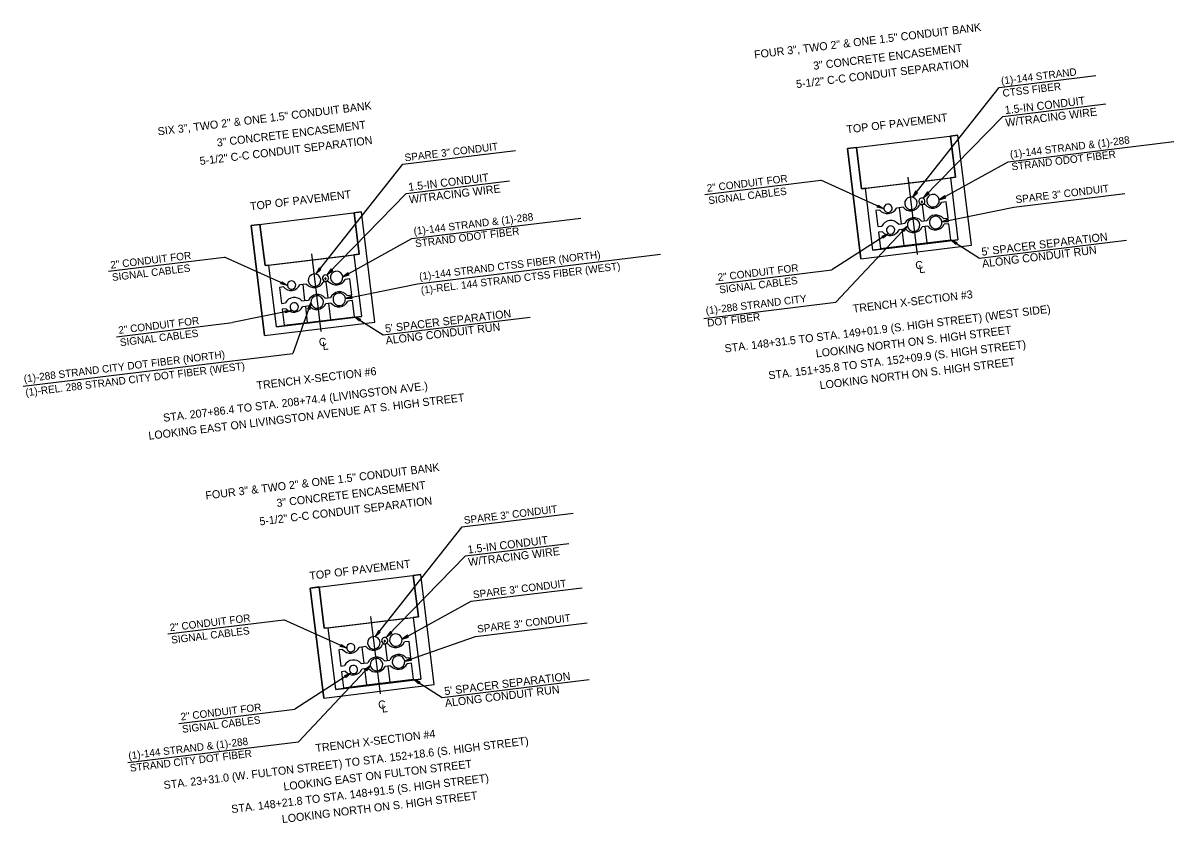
# Model space of a CAD drawing. Extents: x 91401 to 1830080, y 35587 to 712188.
# Drawn here: x 1828619 to 1829481, y 710434 to 711034 of the extents above; entities that cross this region are included whole.
import ezdxf

# ---------------------------------------------------------------- set-up
doc = ezdxf.new("R2010")
doc.units = 0
doc.layers.add('Default', color=7, linetype='Continuous')
doc.layers.add('SH_Text', color=7, linetype='Continuous')

# ---------------------------------------------------------------- blocks, each defined once
blk = doc.blocks.new('POINT_DISPLAY')
at = {"layer": 'Default'}
blk.add_line((0, 0), (0, 0), dxfattribs=at)

msp = doc.modelspace()

# ---------------------------------------------------------------- linework, layer by layer
at = {"layer": 'SH_Text'}
for p, q in [((1829350.31, 710985.54), (1829422.8, 710994.39)), ((1829285.23, 710903.22), (1829350.31, 710985.54)), ((1829352.97, 710963.73), (1829430.34, 710973.18)), ((1829293.65, 710903.03), (1829352.97, 710963.73)), ((1829319.39, 710949.8), (1829313.8, 710949.12)), ((1829317.58, 710918.16), (1829313.8, 710949.12)), ((1829329.47, 710867.28), (1829319.39, 710949.8)), ((1829243.26, 710940.51), (1829236.55, 710939.69)), ((1829236.55, 710939.69), (1829246.63, 710857.17)), ((1829247.04, 710909.55), (1829243.26, 710940.51)), ((1829357.12, 710929.79), (1829481.34, 710944.96)), ((1828903.24, 710927.93), (1828987.77, 710938.25)), ((1828838.16, 710845.62), (1828903.24, 710927.93)), ((1829305.38, 710901.24), (1829357.12, 710929.79)), ((1828905.9, 710906.13), (1828983.27, 710915.58)), ((1829129.75, 710905.34), (1829216.65, 710915.95)), ((1829263.85, 710894.59), (1829216.65, 710915.95)), ((1829281.76, 710918.38), (1829288.85, 710860.29)), ((1829313.74, 710917.69), (1829319.4, 710871.37)), ((1828846.57, 710845.42), (1828905.9, 710906.13)), ((1829250.02, 710909.91), (1829247.04, 710909.55)), ((1829255.68, 710863.59), (1829250.02, 710909.91)), ((1829361.26, 710895.89), (1829444.54, 710906.06)), ((1829307.37, 710884.89), (1829361.26, 710895.89)), ((1828872.32, 710892.2), (1828866.73, 710891.52)), ((1828870.51, 710860.56), (1828866.73, 710891.52)), ((1828882.39, 710809.68), (1828872.32, 710892.2)), ((1828910.04, 710872.19), (1829036.73, 710887.65)), ((1828796.19, 710882.9), (1828789.48, 710882.09)), ((1828789.48, 710882.09), (1828799.55, 710799.56)), ((1828799.97, 710851.95), (1828796.19, 710882.9)), ((1829281.5, 710881.74), (1829227.81, 710824.53)), ((1828858.3, 710843.63), (1828910.04, 710872.19)), ((1829267.22, 710876.02), (1829224.85, 710848.81)), ((1829255.68, 710863.59), (1829319.4, 710871.37)), ((1829255.68, 710863.59), (1829319.4, 710871.37)), ((1829255.68, 710863.59), (1829319.4, 710871.37)), ((1829319.4, 710871.37), (1829255.68, 710863.59)), ((1829314.02, 710871.33), (1829335.52, 710857.61)), ((1829335.52, 710857.61), (1829445.72, 710871.06)), ((1829246.63, 710857.17), (1829329.47, 710867.28)), ((1829246.63, 710857.17), (1829329.47, 710867.28)), ((1828682.67, 710847.74), (1828769.58, 710858.35)), ((1828816.77, 710836.98), (1828769.58, 710858.35)), ((1828834.69, 710860.77), (1828841.78, 710802.69)), ((1828866.67, 710860.09), (1828872.32, 710813.77)), ((1828914.18, 710838.28), (1829096.36, 710860.53)), ((1828802.95, 710852.31), (1828799.97, 710851.95)), ((1828808.6, 710805.99), (1828802.95, 710852.31)), ((1829137.95, 710838.2), (1829224.85, 710848.81)), ((1828860.3, 710827.29), (1828914.18, 710838.28)), ((1828820.14, 710818.41), (1828775.57, 710809.24)), ((1828834.42, 710824.13), (1828820.77, 710786.21)), ((1829129.03, 710812.47), (1829227.81, 710824.53)), ((1828799.55, 710799.56), (1828882.39, 710809.68)), ((1828799.55, 710799.56), (1828882.39, 710809.68)), ((1828808.6, 710805.99), (1828872.32, 710813.77)), ((1828808.6, 710805.99), (1828872.32, 710813.77)), ((1828808.6, 710805.99), (1828872.32, 710813.77)), ((1828872.32, 710813.77), (1828808.6, 710805.99)), ((1828866.95, 710813.72), (1828888.44, 710800)), ((1828888.44, 710800), (1828998.65, 710813.46)), ((1828688.67, 710798.63), (1828775.57, 710809.24)), ((1828618.56, 710761.52), (1828820.77, 710786.21)), ((1828947.66, 710656.2), (1829031.03, 710666.38)), ((1828882.58, 710573.89), (1828947.66, 710656.2)), ((1828950.32, 710634.4), (1829027.69, 710643.84)), ((1828891, 710573.69), (1828950.32, 710634.4)), ((1828916.74, 710620.46), (1828911.15, 710619.78)), ((1828926.82, 710537.94), (1828916.74, 710620.46)), ((1828840.61, 710611.17), (1828833.9, 710610.35)), ((1828844.39, 710580.21), (1828840.61, 710611.17)), ((1828914.93, 710588.82), (1828911.15, 710619.78)), ((1828833.9, 710610.35), (1828843.98, 710527.83)), ((1828954.46, 710600.45), (1829037.59, 710610.6)), ((1828902.72, 710571.9), (1828954.46, 710600.45)), ((1828727.1, 710576), (1828814, 710586.61)), ((1828861.19, 710565.25), (1828814, 710586.61)), ((1828879.11, 710589.04), (1828886.2, 710530.95)), ((1828911.09, 710588.36), (1828916.75, 710542.04)), ((1828847.37, 710580.58), (1828844.39, 710580.21)), ((1828853.02, 710534.26), (1828847.37, 710580.58)), ((1828957.69, 710574.03), (1829041.35, 710584.25)), ((1828904.72, 710555.56), (1828957.69, 710574.03)), ((1828878.85, 710552.4), (1828825.16, 710495.19)), ((1828864.57, 710546.68), (1828822.2, 710519.47)), ((1828843.98, 710527.83), (1828926.82, 710537.94)), ((1828843.98, 710527.83), (1828926.82, 710537.94)), ((1828853.02, 710534.26), (1828916.75, 710542.04)), ((1828853.02, 710534.26), (1828916.75, 710542.04)), ((1828853.02, 710534.26), (1828916.75, 710542.04)), ((1828853.02, 710534.26), (1828916.75, 710542.04)), ((1828916.75, 710542.04), (1828853.02, 710534.26)), ((1828911.37, 710541.99), (1828932.87, 710528.27)), ((1828932.87, 710528.27), (1829043.07, 710541.72)), ((1828735.29, 710508.86), (1828822.2, 710519.47)), ((1828697.13, 710479.56), (1828825.16, 710495.19))]:
    msp.add_line(p, q, dxfattribs=at)
for points in [[(1829236.55, 710939.69), (1829307.1, 710948.3), (1829319.39, 710949.8), (1829319.39, 710949.8)], [(1829243.26, 710940.51), (1829247.04, 710909.55), (1829317.58, 710918.16), (1829313.8, 710949.12)], [(1829313.8, 710949.12), (1829317.58, 710918.16), (1829313.74, 710917.69)], [(1829329.47, 710867.28), (1829319.39, 710949.8)], [(1829246.63, 710857.17), (1829236.55, 710939.69)], [(1829250.02, 710909.91), (1829290.58, 710914.87), (1829313.74, 710917.69), (1829319.4, 710871.37)], [(1829250.02, 710909.91), (1829308.4, 710917.04), (1829313.74, 710917.69), (1829319.4, 710871.37)], [(1829250.02, 710909.91), (1829272.77, 710912.69), (1829313.74, 710917.69), (1829319.4, 710871.37)], [(1829255.68, 710863.59), (1829250.02, 710909.91)], [(1829255.68, 710863.59), (1829250.02, 710909.91)], [(1829294.72, 710897.76), (1829290.67, 710897.27)], [(1829292.69, 710897.52), (1829294.16, 710885.48)], [(1829308.64, 710887.25), (1829312.03, 710887.66), (1829310.56, 710899.7), (1829307.17, 710899.28)], [(1828789.48, 710882.09), (1828860.02, 710890.7), (1828872.32, 710892.2), (1828872.32, 710892.2)], [(1828796.19, 710882.9), (1828799.97, 710851.95), (1828870.51, 710860.56), (1828866.73, 710891.52)], [(1828866.73, 710891.52), (1828870.51, 710860.56), (1828866.67, 710860.09)], [(1828882.39, 710809.68), (1828872.32, 710892.2)], [(1829260.82, 710893.62), (1829257.89, 710893.27), (1829259.36, 710881.23), (1829262.29, 710881.58)], [(1829275.29, 710895.39), (1829273.27, 710895.14)], [(1829278.22, 710895.75), (1829275.29, 710895.39), (1829276.76, 710883.35)], [(1828799.55, 710799.56), (1828789.48, 710882.09)], [(1829274.74, 710883.11), (1829276.76, 710883.35)], [(1829277.29, 710879.06), (1829275.26, 710878.81)], [(1829276.76, 710883.35), (1829279.69, 710883.71)], [(1829280.21, 710879.42), (1829277.29, 710879.06), (1829278.76, 710867.02)], [(1829278.76, 710867.02), (1829314.02, 710871.33), (1829312.55, 710883.37), (1829309.17, 710882.95)], [(1829292.14, 710885.23), (1829296.19, 710885.72)], [(1829296.72, 710881.43), (1829292.66, 710880.94)], [(1829294.69, 710881.18), (1829296.16, 710869.15)], [(1829262.81, 710877.29), (1829259.89, 710876.93), (1829261.35, 710864.9), (1829278.76, 710867.02)], [(1828802.95, 710852.31), (1828843.51, 710857.26), (1828866.67, 710860.09), (1828872.32, 710813.77)], [(1828802.95, 710852.31), (1828861.32, 710859.44), (1828866.67, 710860.09), (1828872.32, 710813.77)], [(1828802.95, 710852.31), (1828825.7, 710855.09), (1828866.67, 710860.09), (1828872.32, 710813.77)], [(1828808.6, 710805.99), (1828802.95, 710852.31)], [(1828808.6, 710805.99), (1828802.95, 710852.31)], [(1828813.74, 710836.02), (1828810.82, 710835.66), (1828812.29, 710823.62), (1828815.21, 710823.98)], [(1828828.22, 710837.79), (1828826.19, 710837.54)], [(1828831.14, 710838.14), (1828828.22, 710837.79), (1828829.69, 710825.75)], [(1828847.65, 710840.16), (1828843.59, 710839.66)], [(1828845.62, 710839.91), (1828847.09, 710827.87)], [(1828861.57, 710829.64), (1828864.96, 710830.06), (1828863.49, 710842.09), (1828860.1, 710841.68)], [(1828845.06, 710827.63), (1828849.12, 710828.12)], [(1828815.73, 710819.69), (1828812.81, 710819.33), (1828814.28, 710807.29), (1828831.68, 710809.42)], [(1828827.66, 710825.5), (1828829.69, 710825.75)], [(1828830.21, 710821.46), (1828828.19, 710821.21)], [(1828829.69, 710825.75), (1828832.61, 710826.11)], [(1828833.14, 710821.81), (1828830.21, 710821.46), (1828831.68, 710809.42)], [(1828831.68, 710809.42), (1828866.95, 710813.72), (1828865.48, 710825.76), (1828862.09, 710825.35)], [(1828849.64, 710823.83), (1828845.59, 710823.33)], [(1828847.61, 710823.58), (1828849.08, 710811.54)], [(1828833.9, 710610.35), (1828904.44, 710618.96), (1828916.74, 710620.46), (1828916.74, 710620.46)], [(1828926.82, 710537.94), (1828916.74, 710620.46)], [(1828840.61, 710611.17), (1828844.39, 710580.21), (1828914.93, 710588.82), (1828911.15, 710619.78)], [(1828911.15, 710619.78), (1828914.93, 710588.82), (1828911.09, 710588.36)], [(1828843.98, 710527.83), (1828833.9, 710610.35)], [(1828847.37, 710580.58), (1828887.93, 710585.53), (1828911.09, 710588.36), (1828916.75, 710542.04)], [(1828847.37, 710580.58), (1828887.93, 710585.53), (1828911.09, 710588.36), (1828916.75, 710542.04)], [(1828847.37, 710580.58), (1828905.74, 710587.7), (1828911.09, 710588.36), (1828916.75, 710542.04)], [(1828847.37, 710580.58), (1828870.12, 710583.35), (1828911.09, 710588.36), (1828916.75, 710542.04)], [(1828853.02, 710534.26), (1828847.37, 710580.58)], [(1828853.02, 710534.26), (1828847.37, 710580.58)], [(1828892.07, 710568.42), (1828888.02, 710567.93)], [(1828890.04, 710568.18), (1828891.51, 710556.14)], [(1828905.99, 710557.91), (1828909.38, 710558.32), (1828907.91, 710570.36), (1828904.52, 710569.94)], [(1828858.16, 710564.28), (1828855.24, 710563.93), (1828856.71, 710551.89), (1828859.63, 710552.25)], [(1828872.64, 710566.05), (1828870.61, 710565.8)], [(1828875.57, 710566.41), (1828872.64, 710566.05), (1828874.11, 710554.01)], [(1828872.08, 710553.77), (1828874.11, 710554.01)], [(1828874.11, 710554.01), (1828877.04, 710554.37)], [(1828876.1, 710537.68), (1828911.37, 710541.99), (1828909.9, 710554.03), (1828906.51, 710553.61)], [(1828889.49, 710555.89), (1828893.54, 710556.39)], [(1828894.06, 710552.09), (1828890.01, 710551.6)], [(1828892.04, 710551.85), (1828893.51, 710539.81)], [(1828860.16, 710547.95), (1828857.23, 710547.6), (1828858.7, 710535.56), (1828876.1, 710537.68)], [(1828874.63, 710549.72), (1828872.61, 710549.47)], [(1828877.56, 710550.08), (1828874.63, 710549.72), (1828876.1, 710537.68)]]:
    msp.add_lwpolyline(points, dxfattribs=at)
for points in [[(1829288.99, 710906.63), (1829287.68, 710907.66), (1829285.23, 710903.22)], [(1829297.76, 710905.99), (1829296.58, 710907.16), (1829293.65, 710903.03)], [(1829258.95, 710895.89), (1829259.64, 710897.41), (1829263.85, 710894.59)], [(1829310.21, 710902.76), (1829309.45, 710904.25), (1829305.38, 710901.24)], [(1829278.69, 710877.52), (1829277.47, 710878.66), (1829281.5, 710881.74)], [(1829312.44, 710885.09), (1829312.1, 710886.72), (1829307.37, 710884.89)], [(1829263.46, 710872.61), (1829262.56, 710874.02), (1829267.22, 710876.02)], [(1829318.68, 710869.33), (1829317.78, 710867.93), (1829314.02, 710871.33)], [(1828841.91, 710849.03), (1828840.6, 710850.06), (1828838.16, 710845.62)], [(1828850.69, 710848.38), (1828849.51, 710849.56), (1828846.57, 710845.42)], [(1828863.14, 710845.16), (1828862.38, 710846.64), (1828858.3, 710843.63)], [(1828811.87, 710838.29), (1828812.56, 710839.8), (1828816.77, 710836.98)], [(1828865.36, 710827.48), (1828865.03, 710829.12), (1828860.3, 710827.29)], [(1828815.42, 710816.59), (1828815.08, 710818.22), (1828820.14, 710818.41)], [(1828833.51, 710819.15), (1828831.95, 710819.71), (1828834.42, 710824.13)], [(1828871.61, 710811.73), (1828870.71, 710810.33), (1828866.95, 710813.72)], [(1828886.33, 710577.29), (1828885.03, 710578.33), (1828882.58, 710573.89)], [(1828895.11, 710576.65), (1828893.93, 710577.82), (1828891, 710573.69)], [(1828856.3, 710566.55), (1828856.98, 710568.07), (1828861.19, 710565.25)], [(1828907.56, 710573.42), (1828906.8, 710574.91), (1828902.72, 710571.9)], [(1828876.03, 710548.18), (1828874.82, 710549.32), (1828878.85, 710552.4)], [(1828909.73, 710556.3), (1828909.22, 710557.89), (1828904.72, 710555.56)], [(1828860.81, 710543.28), (1828859.91, 710544.68), (1828864.57, 710546.68)], [(1828916.03, 710539.99), (1828915.13, 710538.59), (1828911.37, 710541.99)]]:
    msp.add_lwpolyline(points, close=True, dxfattribs=at)
for centre, radius, start, end in [((1829300.71, 710900.67), 4.7, 6.96143, 186.96143), ((1829266.96, 710894.97), 3.13, 6.96143, 186.96143), ((1829283.96, 710900.5), 7.45, 219.64855, 334.27431), ((1829284.17, 710898.65), 4.7, 6.96143, 186.96143), ((1829284.17, 710898.65), 4.7, 186.96143, 6.96143), ((1829292.37, 710900.25), 2.35, 6.96143, 186.96143), ((1829292.37, 710900.25), 2.35, 186.96143, 6.96143), ((1829292.35, 710899.85), 0.5, 6.96143, 186.96143), ((1829292.35, 710899.85), 0.5, 186.96143, 6.96143), ((1829300.46, 710902.52), 7.45, 219.64855, 334.27431), ((1829300.71, 710900.67), 4.7, 186.96143, 6.96143), ((1829266.55, 710898.38), 7.45, 219.64855, 334.27431), ((1829266.96, 710894.97), 3.13, 186.96143, 6.96143), ((1829286.4, 710880.48), 7.45, 39.64855, 154.27431), ((1829302.9, 710882.49), 7.45, 39.64855, 154.27431), ((1829302.71, 710884.32), 4.7, 6.96143, 186.96143), ((1829269, 710878.35), 7.45, 39.64855, 154.27431), ((1829268.55, 710882.05), 7.45, 219.64855, 334.27431), ((1829268.95, 710878.63), 3.13, 6.96143, 186.96143), ((1829268.95, 710878.63), 3.13, 186.96143, 6.96143), ((1829285.95, 710884.17), 7.45, 219.64855, 334.27431), ((1829286.16, 710882.31), 4.7, 6.96143, 186.96143), ((1829286.16, 710882.31), 4.7, 186.96143, 6.96143), ((1829302.45, 710886.19), 7.45, 219.64855, 334.27431), ((1829302.71, 710884.32), 4.7, 186.96143, 6.96143), ((1828837.09, 710841.04), 4.7, 6.96143, 186.96143), ((1828845.29, 710842.65), 2.35, 6.96143, 186.96143), ((1828853.64, 710843.06), 4.7, 6.96143, 186.96143), ((1828819.48, 710840.77), 7.45, 219.64855, 334.27431), ((1828819.88, 710837.36), 3.13, 6.96143, 186.96143), ((1828819.88, 710837.36), 3.13, 186.96143, 6.96143), ((1828836.88, 710842.9), 7.45, 219.64855, 334.27431), ((1828837.09, 710841.04), 4.7, 186.96143, 6.96143), ((1828845.29, 710842.65), 2.35, 186.96143, 6.96143), ((1828845.27, 710842.24), 0.5, 6.96143, 186.96143), ((1828845.27, 710842.24), 0.5, 186.96143, 6.96143), ((1828853.38, 710844.91), 7.45, 219.64855, 334.27431), ((1828853.64, 710843.06), 4.7, 186.96143, 6.96143), ((1828821.92, 710820.75), 7.45, 39.64855, 154.27431), ((1828839.33, 710822.87), 7.45, 39.64855, 154.27431), ((1828839.09, 710824.7), 4.7, 6.96143, 186.96143), ((1828855.83, 710824.89), 7.45, 39.64855, 154.27431), ((1828855.63, 710826.72), 4.7, 6.96143, 186.96143), ((1828855.63, 710826.72), 4.7, 186.96143, 6.96143), ((1828821.47, 710824.44), 7.45, 219.64855, 334.27431), ((1828821.88, 710821.02), 3.13, 6.96143, 186.96143), ((1828821.88, 710821.02), 3.13, 186.96143, 6.96143), ((1828838.87, 710826.57), 7.45, 219.64855, 334.27431), ((1828839.09, 710824.7), 4.7, 186.96143, 6.96143), ((1828855.38, 710828.58), 7.45, 219.64855, 334.27431), ((1828864.3, 710565.63), 3.13, 6.96143, 186.96143), ((1828881.52, 710569.31), 4.7, 6.96143, 186.96143), ((1828881.52, 710569.31), 4.7, 186.96143, 6.96143), ((1828889.71, 710570.92), 2.35, 6.96143, 186.96143), ((1828889.71, 710570.92), 2.35, 186.96143, 6.96143), ((1828889.69, 710570.51), 0.5, 6.96143, 186.96143), ((1828889.69, 710570.51), 0.5, 186.96143, 6.96143), ((1828897.81, 710573.18), 7.45, 219.64855, 334.27431), ((1828898.06, 710571.33), 4.7, 6.96143, 186.96143), ((1828898.06, 710571.33), 4.7, 186.96143, 6.96143), ((1828863.9, 710569.04), 7.45, 219.64855, 334.27431), ((1828864.3, 710565.63), 3.13, 186.96143, 6.96143), ((1828881.3, 710571.16), 7.45, 219.64855, 334.27431), ((1828900.25, 710553.15), 7.45, 39.64855, 154.27431), ((1828900.05, 710554.99), 4.7, 6.96143, 186.96143), ((1828866.35, 710549.01), 7.45, 39.64855, 154.27431), ((1828866.3, 710549.29), 3.13, 6.96143, 186.96143), ((1828883.75, 710551.14), 7.45, 39.64855, 154.27431), ((1828883.3, 710554.83), 7.45, 219.64855, 334.27431), ((1828883.51, 710552.97), 4.7, 6.96143, 186.96143), ((1828883.51, 710552.97), 4.7, 186.96143, 6.96143), ((1828899.8, 710556.85), 7.45, 219.64855, 334.27431), ((1828900.05, 710554.99), 4.7, 186.96143, 6.96143), ((1828865.89, 710552.71), 7.45, 219.64855, 334.27431), ((1828866.3, 710549.29), 3.13, 186.96143, 6.96143)]:
    msp.add_arc(centre, radius, start, end, dxfattribs=at)

# ---------------------------------------------------------------- block references
at = {"layer": 'SH_Text', "xscale": 1.5748, "yscale": 1.5748000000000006, "rotation": 6.96142799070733}
for p in [(1829288.02, 710867.15), (1828840.94, 710809.54), (1828885.36, 710537.81)]:
    msp.add_blockref('POINT_DISPLAY', p, dxfattribs=at)

# ---------------------------------------------------------------- texts
at = {"layer": 'SH_Text'}
for s, height, p in [('FOUR 3", TWO 2" & ONE 1.5" CONDUIT BANK', 6, (1829167, 711007.13)), ('3" CONCRETE ENCASEMENT', 6, (1829211.27, 710998.73)), ('5-1/2" C-C CONDUIT SEPARATION', 6, (1829198.44, 710984.97)), ('(1)-144 STRAND', 5.6, (1829352.05, 710987.71)), ('CTSS FIBER', 5.6, (1829353.18, 710978.44)), ('SIX 3", TWO 2" & ONE 1.5" CONDUIT BANK', 6, (1828719.92, 710949.53)), ('1.5-IN CONDUIT', 6, (1829354.85, 710965.49)), ('TOP OF PAVEMENT', 6, (1829236.2, 710951)), ('W/TRACING WIRE', 6, (1829355.35, 710956.14)), ('3" CONCRETE ENCASEMENT', 6, (1828764.19, 710941.13)), ('5-1/2" C-C CONDUIT SEPARATION', 6, (1828751.36, 710927.36)), ('(1)-144 STRAND & (1)-288 ', 5.6, (1829358.78, 710932.6)), ('SPARE 3" CONDUIT', 5.6, (1828904.98, 710930.11)), ('STRAND ODOT FIBER', 5.6, (1829359.91, 710923.33)), ('1.5-IN CONDUIT', 6, (1828907.78, 710907.89)), ('2" CONDUIT FOR ', 5.6, (1829131.52, 710907.25)), ('TOP OF PAVEMENT', 6, (1828789.12, 710893.4)), ('W/TRACING WIRE', 6, (1828908.28, 710898.54)), ('SIGNAL CABLES', 5.6, (1829132.65, 710897.98)), ('SPARE 3" CONDUIT', 5.6, (1829362.92, 710898.69)), ('(1)-144 STRAND & (1)-288 ', 5.6, (1828911.71, 710874.99)), ('STRAND ODOT FIBER ', 5.6, (1828912.84, 710865.73)), ("5' SPACER SEPARATION", 6, (1829337.4, 710859.36)), ('2" CONDUIT FOR ', 5.6, (1828684.45, 710849.64)), ('(1)-144 STRAND CTSS FIBER (NORTH)', 5.6, (1828915.85, 710841.09)), ('ALONG CONDUIT RUN', 6, (1829337.84, 710850.48)), ('SIGNAL CABLES', 5.6, (1828685.58, 710840.38)), ('(1)-REL. 144 STRAND CTSS FIBER (WEST)', 5.6, (1828917.11, 710830.77)), ('2" CONDUIT FOR ', 5.6, (1829139.69, 710840.37)), ('C', 6, (1829287.81, 710849.06)), ('L', 6, (1829290.5, 710846.26)), ('SIGNAL CABLES', 5.6, (1829140.82, 710831.11)), ('(1)-288 STRAND CITY ', 5.6, (1829130.67, 710815.45)), ('TRENCH X-SECTION #3', 6, (1829240.92, 710816.71)), ("5' SPACER SEPARATION", 6, (1828890.32, 710801.76)), ('STA. 148+31.5 TO STA. 149+01.9 (S. HIGH STREET) (WEST SIDE)', 6, (1829144.83, 710786.88)), ('2" CONDUIT FOR ', 5.6, (1828690.41, 710800.81)), ('DOT FIBER', 5.6, (1829131.8, 710806.18)), ('SIGNAL CABLES', 5.6, (1828691.54, 710791.54)), ('ALONG CONDUIT RUN', 6, (1828890.77, 710792.88)), ('LOOKING NORTH ON S. HIGH STREET', 6, (1829213.22, 710783.14)), ('C', 6, (1828840.73, 710791.45)), ('L', 6, (1828843.43, 710788.66)), ('STA. 151+35.8 TO STA. 152+09.9 (S. HIGH STREET)', 6, (1829177.66, 710766.71)), ('(1)-288 STRAND CITY DOT FIBER (NORTH)', 5.6, (1828619.48, 710764.41)), ('(1)-REL. 288 STRAND CITY DOT FIBER (WEST)', 5.6, (1828620.74, 710754.09)), ('TRENCH X-SECTION #6', 6, (1828793.99, 710759.12)), ('LOOKING NORTH ON S. HIGH STREET', 6, (1829216.13, 710759.32)), ('STA. 207+86.4 TO STA. 208+74.4 (LIVINGSTON AVE.)', 6, (1828723.98, 710734.89)), ('LOOKING EAST ON LIVINGSTON AVENUE AT S. HIGH STREET', 6, (1828712.96, 710721.46)), ('FOUR 3" & TWO 2" & ONE 1.5" CONDUIT BANK', 6, (1828755.71, 710676.71)), ('3" CONCRETE ENCASEMENT', 6, (1828808.96, 710671.02)), ('5-1/2" C-C CONDUIT SEPARATION', 6, (1828796.13, 710657.25)), ('SPARE 3" CONDUIT', 5.6, (1828949.4, 710658.37)), ('1.5-IN CONDUIT', 6, (1828952.2, 710636.15)), ('W/TRACING WIRE', 6, (1828952.7, 710626.8)), ('TOP OF PAVEMENT', 6, (1828833.61, 710616.47)), ('SPARE 3" CONDUIT', 5.6, (1828956.21, 710602.62)), ('2" CONDUIT FOR ', 5.6, (1828728.87, 710577.91)), ('SPARE 3" CONDUIT', 5.6, (1828959.36, 710576.84)), ('SIGNAL CABLES', 5.6, (1828730, 710568.64)), ("5' SPACER SEPARATION", 6, (1828934.74, 710530.02)), ('ALONG CONDUIT RUN', 6, (1828935.19, 710521.14)), ('C', 6, (1828885.16, 710519.72)), ('2" CONDUIT FOR ', 5.6, (1828737.04, 710511.03)), ('L', 6, (1828887.85, 710516.92)), ('SIGNAL CABLES', 5.6, (1828738.17, 710501.77)), ('STA. 23+31.0 (W. FULTON STREET) TO STA. 152+18.6 (S. HIGH STREET)', 6, (1828724.37, 710459.64)), ('TRENCH X-SECTION #4', 6, (1828838.13, 710487.35)), ('(1)-144 STRAND & (1)-288 ', 5.6, (1828697.91, 710481.9)), ('STRAND CITY DOT FIBER', 5.6, (1828699.04, 710472.63)), ('LOOKING EAST ON FULTON STREET', 6, (1828814.16, 710458.51)), ('STA. 148+21.8 TO STA. 148+91.5 (S. HIGH STREET)', 6, (1828775.06, 710441.65)), ('LOOKING NORTH ON S. HIGH STREET', 6, (1828812.96, 710434.19))]:
    msp.add_text(s, height=height, rotation=6.96143, dxfattribs=at).set_placement(p)

doc.saveas('drawing.dxf')
